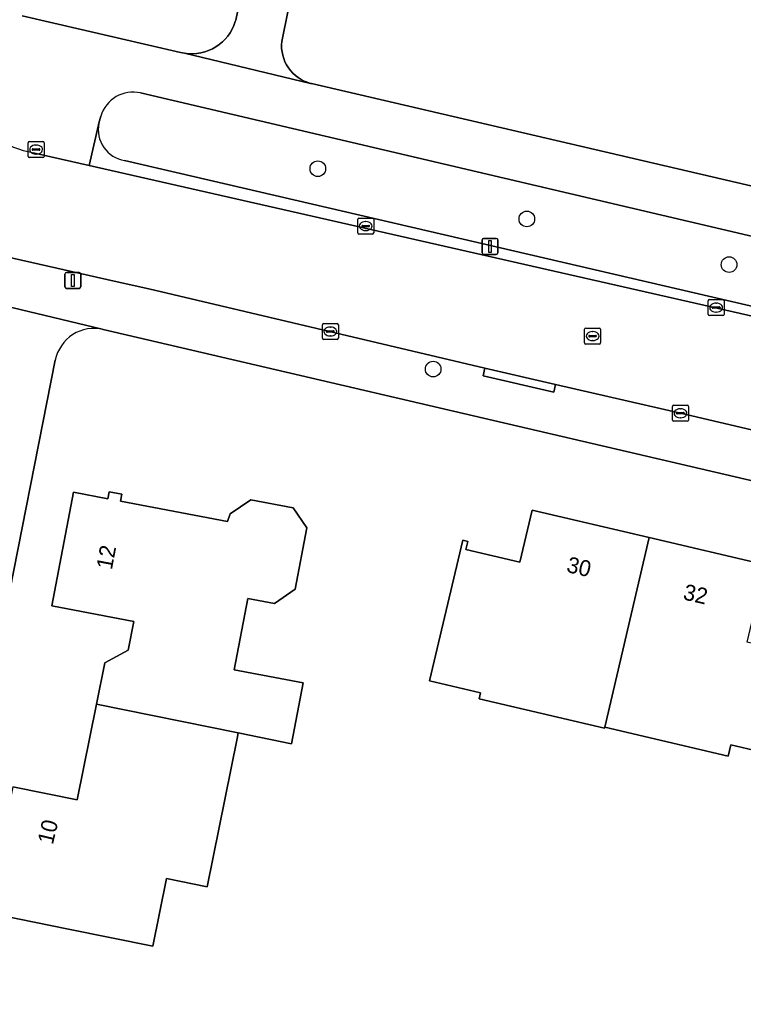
# Model space of a CAD drawing. Extents: x 162184 to 163154, y 385507 to 386516.
# Drawn here: x 162501.1 to 162546.4, y 385816.4 to 385877.3 of the extents above; entities that cross this region are included whole.
import ezdxf

# ---------------------------------------------------------------- set-up
doc = ezdxf.new("R2010")
doc.units = 0
for name, color, linetype in [('IMGEO_Boom', 7, 'Continuous'), ('IMGEO_Erf', 7, 'Continuous'), ('IMGEO_Groenvoorziening', 7, 'Continuous'), ('IMGEO_Kolk', 7, 'Continuous'), ('IMGEO_Lichtmast', 7, 'Continuous'), ('IMGEO_Pand', 7, 'Continuous'), ('IMGEO_Pand_nummerreeks', 7, 'Continuous'), ('IMGEO_Rijbaan_lokaal_open', 7, 'Continuous'), ('IMGEO_Rioolput', 7, 'Continuous'), ('IMGEO_Voetpad_open', 7, 'Continuous')]:
    doc.layers.add(name, color=color, linetype=linetype)

msp = doc.modelspace()

# ---------------------------------------------------------------- linework, layer by layer
at = {"layer": 'IMGEO_Boom'}
for centre in [(162519.792, 385867.979), (162532.864, 385864.836), (162545.515, 385861.981), (162527.005, 385855.455)]:
    msp.add_circle(centre, 0.489, dxfattribs=at)
at = {"layer": 'IMGEO_Erf'}
for points in [[(162530.251, 385938.589), (162517.573, 385876.141), (162517.539, 385875.927), (162517.525, 385875.711), (162517.53, 385875.495), (162517.554, 385875.28), (162517.597, 385875.068), (162517.659, 385874.861), (162517.739, 385874.66), (162517.837, 385874.467), (162517.952, 385874.284), (162518.083, 385874.111), (162518.228, 385873.951), (162518.388, 385873.805), (162518.559, 385873.673), (162518.742, 385873.557), (162518.935, 385873.459), (162519.135, 385873.377), (162519.342, 385873.314), (162519.391, 385873.302), (162708.853, 385829.198)], [(162699.173, 385813.033), (162656.753, 385822.985), (162635.665, 385827.646), (162589.44, 385838.573), (162506.371, 385857.936)], [(162503.373, 385856.006), (162500, 385838.961), (162491.51, 385796.057)], [(162500.718, 385829.346), (162504.748, 385828.532), (162505.954, 385834.504), (162506.479, 385837.102), (162507.941, 385837.89), (162508.283, 385839.679), (162503.148, 385840.658), (162504.503, 385847.764), (162506.65, 385847.354), (162506.732, 385847.779), (162507.526, 385847.628), (162507.444, 385847.194), (162514.139, 385845.929), (162514.311, 385846.403), (162515.601, 385847.28), (162518.253, 385846.774), (162519.102, 385845.525), (162518.372, 385841.694), (162517.075, 385840.81), (162515.417, 385841.125), (162514.567, 385836.666), (162518.88, 385835.845), (162518.156, 385832.041), (162514.819, 385832.715), (162514.746, 385832.356), (162512.872, 385823.1), (162510.331, 385823.614), (162509.477, 385819.385), (162504.208, 385820.449), (162500, 385821.299)], [(162549.176, 385831.126), (162545.626, 385831.959), (162545.464, 385831.267), (162537.747, 385833.078), (162537.73, 385833.003), (162529.874, 385834.847), (162529.961, 385835.216), (162526.786, 385835.962), (162528.853, 385844.76), (162529.164, 385844.686), (162529.045, 385844.179), (162532.432, 385843.383), (162533.198, 385846.644), (162540.507, 385844.929), (162547.788, 385843.22)]]:
    msp.add_lwpolyline(points, dxfattribs=at)
msp.add_arc((162505.806, 385855.52), 2.482, 76.84914, 168.6947, dxfattribs=at)
at = {"layer": 'IMGEO_Groenvoorziening'}
for points in [[(162501.3, 385877.523), (162511.214, 385875.241), (162511.464, 385875.19), (162511.717, 385875.162), (162511.971, 385875.156), (162512.225, 385875.174), (162512.477, 385875.214), (162512.724, 385875.276), (162512.964, 385875.36), (162513.196, 385875.465), (162513.417, 385875.59), (162513.627, 385875.735), (162513.823, 385875.898), (162514.003, 385876.077), (162514.167, 385876.272), (162514.312, 385876.481), (162514.439, 385876.702), (162514.545, 385876.934), (162514.63, 385877.174), (162514.655, 385877.262), (162515.874, 385883.146)], [(162507.704, 385868.49), (162547.735, 385859.209), (162547.854, 385859.698), (162548.778, 385863.326), (162508.707, 385872.714)], [(162506.219, 385871.261), (162506.098, 385870.815)]]:
    msp.add_lwpolyline(points, dxfattribs=at)
for centre, radius, start, end in [((162508.235, 385870.666), 2.102, 77.01532, 163.55481), ((162508.015, 385870.422), 1.957, 168.42665, 260.84312)]:
    msp.add_arc(centre, radius, start, end, dxfattribs=at)
at = {"layer": 'IMGEO_Kolk'}
for p, q in [((162501.674, 385868.751), (162501.674, 385869.603)), ((162501.749, 385869.677), (162502.601, 385869.677)), ((162502.675, 385869.603), (162502.675, 385868.751)), ((162501.933, 385869.171), (162501.933, 385869.183)), ((162502.371, 385869.134), (162501.973, 385869.134)), ((162501.976, 385869.22), (162502.374, 385869.22)), ((162502.162, 385869.457), (162502.187, 385869.457)), ((162502.417, 385869.183), (162502.417, 385869.171)), ((162502.601, 385868.677), (162501.749, 385868.677)), ((162502.185, 385868.897), (162502.16, 385868.897)), ((162522.284, 385863.965), (162522.284, 385864.817)), ((162522.359, 385864.891), (162523.211, 385864.891)), ((162523.285, 385864.817), (162523.285, 385863.965)), ((162522.543, 385864.385), (162522.543, 385864.397)), ((162522.981, 385864.348), (162522.583, 385864.348)), ((162522.586, 385864.434), (162522.984, 385864.434)), ((162522.795, 385864.111), (162522.77, 385864.111)), ((162522.772, 385864.671), (162522.797, 385864.671)), ((162523.027, 385864.397), (162523.027, 385864.385)), ((162523.211, 385863.891), (162522.359, 385863.891)), ((162544.203, 385858.869), (162544.203, 385859.721)), ((162544.278, 385859.795), (162545.13, 385859.795)), ((162544.462, 385859.289), (162544.462, 385859.301)), ((162544.9, 385859.252), (162544.502, 385859.252)), ((162544.505, 385859.338), (162544.903, 385859.338)), ((162544.691, 385859.575), (162544.716, 385859.575)), ((162544.946, 385859.301), (162544.946, 385859.289)), ((162545.204, 385859.721), (162545.204, 385858.869)), ((162545.13, 385858.795), (162544.278, 385858.795)), ((162544.714, 385859.015), (162544.689, 385859.015)), ((162520.074, 385857.377), (162520.074, 385858.229)), ((162520.149, 385858.303), (162521.001, 385858.303)), ((162520.562, 385858.083), (162520.587, 385858.083)), ((162521.075, 385858.229), (162521.075, 385857.377)), ((162520.333, 385857.797), (162520.333, 385857.809)), ((162520.771, 385857.76), (162520.373, 385857.76)), ((162520.376, 385857.846), (162520.774, 385857.846)), ((162520.585, 385857.523), (162520.56, 385857.523)), ((162520.817, 385857.809), (162520.817, 385857.797)), ((162521.001, 385857.303), (162520.149, 385857.303)), ((162542.046, 385853.194), (162542.898, 385853.194)), ((162541.971, 385852.268), (162541.971, 385853.12)), ((162542.23, 385852.688), (162542.23, 385852.7)), ((162542.668, 385852.651), (162542.27, 385852.651)), ((162542.273, 385852.737), (162542.671, 385852.737)), ((162542.459, 385852.974), (162542.484, 385852.974)), ((162542.714, 385852.7), (162542.714, 385852.688)), ((162542.972, 385853.12), (162542.972, 385852.268)), ((162542.898, 385852.194), (162542.046, 385852.194)), ((162542.482, 385852.414), (162542.457, 385852.414))]:
    msp.add_line(p, q, dxfattribs=at)
for points in [[(162501.674, 385868.751), (162501.674, 385869.603)], [(162501.749, 385869.677), (162502.601, 385869.677)], [(162502.675, 385869.603), (162502.675, 385868.751)], [(162502.601, 385868.677), (162501.749, 385868.677)], [(162522.284, 385863.965), (162522.284, 385864.817)], [(162522.359, 385864.891), (162523.211, 385864.891)], [(162523.285, 385864.817), (162523.285, 385863.965)], [(162523.211, 385863.891), (162522.359, 385863.891)], [(162544.203, 385858.869), (162544.203, 385859.721)], [(162544.278, 385859.795), (162545.13, 385859.795)], [(162545.204, 385859.721), (162545.204, 385858.869)], [(162545.13, 385858.795), (162544.278, 385858.795)], [(162520.074, 385857.377), (162520.074, 385858.229)], [(162520.149, 385858.303), (162521.001, 385858.303)], [(162521.075, 385858.229), (162521.075, 385857.377)], [(162521.001, 385857.303), (162520.149, 385857.303)], [(162542.046, 385853.194), (162542.898, 385853.194)], [(162541.971, 385852.268), (162541.971, 385853.12)], [(162542.972, 385853.12), (162542.972, 385852.268)], [(162542.898, 385852.194), (162542.046, 385852.194)]]:
    msp.add_lwpolyline(points, dxfattribs=at)
for centre, radius, start, end in [((162501.751, 385869.601), 0.0765, 91.55205, 178.44795), ((162501.751, 385869.601), 0.0765, 91.55205, 178.44795), ((162502.599, 385869.601), 0.0765, 1.55205, 88.44795), ((162502.599, 385869.601), 0.0765, 1.55205, 88.44795), ((162501.973, 385869.18), 0.0403, 85.87752, 175.75265), ((162501.97, 385869.17), 0.0366, 178.93798, 274.71019), ((162502.374, 385869.177), 0.043, 264.86636, 352.45326), ((162502.378, 385869.182), 0.0386, 1.73085, 96.63898), ((162501.751, 385868.753), 0.0765, 181.55205, 268.44795), ((162501.751, 385868.753), 0.0765, 181.55205, 268.44795), ((162502.599, 385868.753), 0.0765, 271.55205, 358.44795), ((162502.599, 385868.753), 0.0765, 271.55205, 358.44795), ((162522.361, 385864.815), 0.0765, 91.55205, 178.44795), ((162522.361, 385864.815), 0.0765, 91.55205, 178.44795), ((162523.209, 385864.815), 0.0765, 1.55205, 88.44795), ((162523.209, 385864.815), 0.0765, 1.55205, 88.44795), ((162522.583, 385864.394), 0.0403, 85.87752, 175.75265), ((162522.58, 385864.384), 0.0366, 178.93798, 274.71019), ((162522.984, 385864.391), 0.043, 264.86636, 352.45326), ((162522.988, 385864.396), 0.0386, 1.73085, 96.63898), ((162522.361, 385863.967), 0.0765, 181.55205, 268.44795), ((162522.361, 385863.967), 0.0765, 181.55205, 268.44795), ((162523.209, 385863.967), 0.0765, 271.55205, 358.44795), ((162523.209, 385863.967), 0.0765, 271.55205, 358.44795), ((162544.28, 385859.719), 0.0765, 91.55205, 178.44795), ((162544.28, 385859.719), 0.0765, 91.55205, 178.44795), ((162544.502, 385859.298), 0.0403, 85.87752, 175.75265), ((162544.499, 385859.288), 0.0366, 178.93798, 274.71019), ((162544.903, 385859.295), 0.043, 264.86636, 352.45326), ((162544.907, 385859.3), 0.0386, 1.73085, 96.63898), ((162545.128, 385859.719), 0.0765, 1.55205, 88.44795), ((162545.128, 385859.719), 0.0765, 1.55205, 88.44795), ((162544.28, 385858.871), 0.0765, 181.55205, 268.44795), ((162544.28, 385858.871), 0.0765, 181.55205, 268.44795), ((162545.128, 385858.871), 0.0765, 271.55205, 358.44795), ((162545.128, 385858.871), 0.0765, 271.55205, 358.44795), ((162520.151, 385858.227), 0.0765, 91.55205, 178.44795), ((162520.151, 385858.227), 0.0765, 91.55205, 178.44795), ((162520.999, 385858.227), 0.0765, 1.55205, 88.44795), ((162520.999, 385858.227), 0.0765, 1.55205, 88.44795), ((162520.373, 385857.806), 0.0403, 85.87752, 175.75265), ((162520.37, 385857.796), 0.0366, 178.93798, 274.71019), ((162520.774, 385857.803), 0.043, 264.86636, 352.45326), ((162520.778, 385857.808), 0.0386, 1.73085, 96.63898), ((162520.151, 385857.379), 0.0765, 181.55205, 268.44795), ((162520.151, 385857.379), 0.0765, 181.55205, 268.44795), ((162520.999, 385857.379), 0.0765, 271.55205, 358.44795), ((162520.999, 385857.379), 0.0765, 271.55205, 358.44795), ((162542.048, 385853.118), 0.0765, 91.55205, 178.44795), ((162542.048, 385853.118), 0.0765, 91.55205, 178.44795), ((162542.896, 385853.118), 0.0765, 1.55205, 88.44795), ((162542.896, 385853.118), 0.0765, 1.55205, 88.44795), ((162542.27, 385852.697), 0.0403, 85.87752, 175.75265), ((162542.267, 385852.687), 0.0366, 178.93798, 274.71019), ((162542.671, 385852.694), 0.043, 264.86636, 352.45326), ((162542.675, 385852.699), 0.0386, 1.73085, 96.63898), ((162542.048, 385852.27), 0.0765, 181.55205, 268.44795), ((162542.048, 385852.27), 0.0765, 181.55205, 268.44795), ((162542.896, 385852.27), 0.0765, 271.55205, 358.44795), ((162542.896, 385852.27), 0.0765, 271.55205, 358.44795)]:
    msp.add_arc(centre, radius, start, end, dxfattribs=at)
for centre, major_axis, ratio, start_param, end_param in [((162502.161, 385869.177), (-0.387, 0.002), 0.722429, 4.712389, 7.853982), ((162502.186, 385869.177), (-0.39, 0.002), 0.717154, 1.570796, 4.712389), ((162522.771, 385864.391), (-0.387, 0.002), 0.722429, 4.712389, 7.853982), ((162522.796, 385864.391), (-0.39, 0.002), 0.717154, 1.570796, 4.712389), ((162544.69, 385859.295), (-0.387, 0.002), 0.722429, 4.712389, 7.853982), ((162544.715, 385859.295), (-0.39, 0.002), 0.717154, 1.570796, 4.712389), ((162520.561, 385857.803), (-0.387, 0.002), 0.722429, 4.712389, 7.853982), ((162520.586, 385857.803), (-0.39, 0.002), 0.717154, 1.570796, 4.712389), ((162542.458, 385852.694), (-0.387, 0.002), 0.722429, 4.712389, 7.853982), ((162542.483, 385852.694), (-0.39, 0.002), 0.717154, 1.570796, 4.712389)]:
    msp.add_ellipse(centre, major_axis=major_axis, ratio=ratio, start_param=start_param, end_param=end_param, dxfattribs=at)
at = {"layer": 'IMGEO_Lichtmast'}
for p, q in [((162530.06, 385862.724), (162530.06, 385863.524)), ((162530.06, 385863.524), (162530.06, 385862.724)), ((162530.16, 385863.624), (162530.95, 385863.624)), ((162530.95, 385863.624), (162530.16, 385863.624)), ((162531.05, 385863.524), (162531.05, 385862.724)), ((162531.05, 385862.724), (162531.05, 385863.524)), ((162530.95, 385862.624), (162530.16, 385862.624)), ((162530.16, 385862.624), (162530.95, 385862.624)), ((162503.974, 385860.597), (162503.974, 385861.397)), ((162503.974, 385861.397), (162503.974, 385860.597)), ((162504.074, 385861.497), (162504.864, 385861.497)), ((162504.864, 385861.497), (162504.074, 385861.497)), ((162504.964, 385861.397), (162504.964, 385860.597)), ((162504.964, 385860.597), (162504.964, 385861.397)), ((162504.864, 385860.497), (162504.074, 385860.497)), ((162504.074, 385860.497), (162504.864, 385860.497))]:
    msp.add_line(p, q, dxfattribs=at)
for points in [[(162530.48, 385863.499), (162530.63, 385863.499), (162530.63, 385862.749), (162530.48, 385862.749), (162530.48, 385863.499)], [(162504.394, 385861.372), (162504.544, 385861.372), (162504.544, 385860.622), (162504.394, 385860.622), (162504.394, 385861.372)]]:
    msp.add_lwpolyline(points, dxfattribs=at)
for centre, start, end in [((162530.16, 385863.524), 90, 180), ((162530.16, 385863.524), 90, 180), ((162530.95, 385863.524), 0, 90), ((162530.95, 385863.524), 360, 90), ((162530.16, 385862.724), 180, 270), ((162530.16, 385862.724), 180, 270), ((162530.95, 385862.724), 270, 0), ((162530.95, 385862.724), 270, 0), ((162504.074, 385861.397), 90, 180), ((162504.074, 385861.397), 90, 180), ((162504.864, 385861.397), 0, 90), ((162504.864, 385861.397), 360, 90), ((162504.074, 385860.597), 180, 270), ((162504.074, 385860.597), 180, 270), ((162504.864, 385860.597), 270, 0), ((162504.864, 385860.597), 270, 0)]:
    msp.add_arc(centre, 0.1, start, end, dxfattribs=at)
at = {"layer": 'IMGEO_Pand'}
for points in [[(162518.372, 385841.694), (162519.102, 385845.525), (162518.253, 385846.774), (162515.601, 385847.28), (162514.311, 385846.403), (162514.139, 385845.929), (162507.444, 385847.194), (162507.526, 385847.628), (162506.732, 385847.779), (162506.65, 385847.354), (162504.503, 385847.764), (162503.148, 385840.658), (162508.283, 385839.679), (162507.941, 385837.89), (162506.479, 385837.102), (162505.954, 385834.504), (162514.819, 385832.715), (162518.156, 385832.041), (162518.88, 385835.845), (162514.567, 385836.666), (162515.417, 385841.125), (162517.075, 385840.81)], [(162540.507, 385844.929), (162533.198, 385846.644), (162532.432, 385843.383), (162529.045, 385844.179), (162529.164, 385844.686), (162528.853, 385844.76), (162526.786, 385835.962), (162529.961, 385835.216), (162529.874, 385834.847), (162537.73, 385833.003), (162537.747, 385833.078)], [(162550.626, 385837.445), (162546.651, 385838.378), (162547.788, 385843.22), (162540.507, 385844.929), (162537.747, 385833.078), (162545.464, 385831.267), (162545.626, 385831.959), (162549.176, 385831.126)], [(162514.746, 385832.356), (162514.819, 385832.715), (162505.954, 385834.504), (162504.748, 385828.532), (162500.718, 385829.346), (162500, 385825.788), (162499.835, 385824.97), (162499.677, 385825.002), (162499.318, 385823.224), (162499.653, 385823.156), (162499.306, 385821.439), (162500, 385821.299), (162504.208, 385820.449), (162509.477, 385819.385), (162510.331, 385823.614), (162512.872, 385823.1)]]:
    msp.add_lwpolyline(points, close=True, dxfattribs=at)
at = {"layer": 'IMGEO_Rijbaan_lokaal_open'}
for points in [[(162610.474, 385844.009), (162603.528, 385845.611), (162603.422, 385845.63), (162587.987, 385849.233), (162580.509, 385850.96), (162566.089, 385854.314), (162562.139, 385855.233), (162554.096, 385857.098), (162547.598, 385858.61), (162505.494, 385868.182), (162501.99, 385868.979)], [(162499.218, 385862.73), (162507.056, 385860.958), (162509.218, 385860.468), (162530.239, 385855.522), (162534.656, 385854.499), (162542.472, 385852.695), (162549.662, 385851.015), (162557.296, 385849.219), (162561.487, 385848.231), (162572.263, 385845.731), (162579.333, 385844.08), (162579.558, 385844.019), (162594.175, 385840.627), (162598.333, 385839.654), (162598.843, 385839.529), (162602.566, 385838.654), (162616.709, 385835.361), (162617.593, 385835.175), (162624.031, 385833.683), (162636.751, 385830.699)]]:
    msp.add_lwpolyline(points, dxfattribs=at)
msp.add_arc((162503.102, 385875.08), 6.201, 165.95967, 259.67133, dxfattribs=at)
at = {"layer": 'IMGEO_Rioolput'}
for p, q in [((162536.553, 385858.016), (162537.405, 385858.016)), ((162536.478, 385857.09), (162536.478, 385857.942)), ((162536.737, 385857.51), (162536.737, 385857.522)), ((162537.175, 385857.473), (162536.777, 385857.473)), ((162536.78, 385857.559), (162537.178, 385857.559)), ((162536.966, 385857.796), (162536.991, 385857.796)), ((162537.221, 385857.522), (162537.221, 385857.51)), ((162537.479, 385857.942), (162537.479, 385857.09)), ((162537.405, 385857.016), (162536.553, 385857.016)), ((162536.989, 385857.236), (162536.964, 385857.236))]:
    msp.add_line(p, q, dxfattribs=at)
for points in [[(162536.553, 385858.016), (162537.405, 385858.016)], [(162536.478, 385857.09), (162536.478, 385857.942)], [(162537.479, 385857.942), (162537.479, 385857.09)], [(162537.405, 385857.016), (162536.553, 385857.016)]]:
    msp.add_lwpolyline(points, dxfattribs=at)
for centre, radius, start, end in [((162536.555, 385857.94), 0.0765, 91.55205, 178.44795), ((162536.555, 385857.94), 0.0765, 91.55205, 178.44795), ((162537.403, 385857.94), 0.0765, 1.55205, 88.44795), ((162537.403, 385857.94), 0.0765, 1.55205, 88.44795), ((162536.777, 385857.519), 0.0403, 85.87752, 175.75265), ((162536.774, 385857.509), 0.0366, 178.93798, 274.71019), ((162537.178, 385857.516), 0.043, 264.86636, 352.45326), ((162537.182, 385857.521), 0.0386, 1.73085, 96.63898), ((162536.555, 385857.092), 0.0765, 181.55205, 268.44795), ((162536.555, 385857.092), 0.0765, 181.55205, 268.44795), ((162537.403, 385857.092), 0.0765, 271.55205, 358.44795), ((162537.403, 385857.092), 0.0765, 271.55205, 358.44795)]:
    msp.add_arc(centre, radius, start, end, dxfattribs=at)
for centre, major_axis, ratio, start_param, end_param in [((162536.965, 385857.516), (-0.387, 0.002), 0.722429, 4.712389, 7.853982), ((162536.99, 385857.516), (-0.39, 0.002), 0.717154, 1.570796, 4.712389)]:
    msp.add_ellipse(centre, major_axis=major_axis, ratio=ratio, start_param=start_param, end_param=end_param, dxfattribs=at)
at = {"layer": 'IMGEO_Voetpad_open'}
for points in [[(162515.874, 385883.146), (162514.655, 385877.262), (162514.63, 385877.174), (162514.545, 385876.934), (162514.439, 385876.702), (162514.312, 385876.481), (162514.167, 385876.272), (162514.003, 385876.077), (162513.823, 385875.898), (162513.627, 385875.735), (162513.417, 385875.59), (162513.196, 385875.465), (162512.964, 385875.36), (162512.724, 385875.276), (162512.477, 385875.214), (162512.225, 385875.174), (162511.971, 385875.156), (162511.717, 385875.162), (162511.464, 385875.19), (162519.342, 385873.314), (162519.135, 385873.377), (162518.935, 385873.459), (162518.742, 385873.557), (162518.559, 385873.673), (162518.388, 385873.805), (162518.228, 385873.951), (162518.083, 385874.111), (162517.952, 385874.284), (162517.837, 385874.467), (162517.739, 385874.66), (162517.659, 385874.861), (162517.597, 385875.068), (162517.554, 385875.28), (162517.53, 385875.495), (162517.525, 385875.711), (162517.539, 385875.927), (162517.573, 385876.141), (162530.251, 385938.589)], [(162519.391, 385873.302), (162519.342, 385873.314), (162511.464, 385875.19), (162511.214, 385875.241), (162501.3, 385877.523)], [(162708.853, 385829.198), (162519.391, 385873.302)], [(162508.707, 385872.714), (162548.778, 385863.326), (162547.854, 385859.698), (162554.349, 385858.155), (162555.24, 385861.819), (162563.244, 385859.94), (162562.391, 385856.309), (162566.335, 385855.374), (162567.186, 385859.042), (162581.626, 385855.694), (162580.763, 385852.023), (162588.234, 385850.294), (162589.092, 385853.966), (162604.684, 385850.342), (162603.81, 385846.69), (162610.724, 385845.075), (162611.587, 385848.755), (162626.899, 385845.211), (162626.065, 385841.525), (162632.616, 385839.977)], [(162501.99, 385868.979), (162505.494, 385868.182), (162506.071, 385870.723), (162506.098, 385870.815), (162506.219, 385871.261)], [(162506.098, 385870.815), (162506.071, 385870.723), (162505.494, 385868.182), (162547.598, 385858.61), (162547.735, 385859.209), (162507.704, 385868.49)], [(162549.662, 385851.015), (162542.472, 385852.695), (162534.656, 385854.499), (162534.544, 385854.012), (162530.127, 385855.035), (162530.239, 385855.522), (162509.218, 385860.468), (162507.056, 385860.958), (162499.218, 385862.73)], [(162496.672, 385860.214), (162498.12, 385859.904), (162506.313, 385857.957), (162506.371, 385857.936), (162589.44, 385838.573), (162635.665, 385827.646), (162656.753, 385822.985), (162699.173, 385813.033)], [(162506.371, 385857.936), (162506.313, 385857.957), (162498.12, 385859.904)], [(162500, 385838.961), (162503.373, 385856.006)]]:
    msp.add_lwpolyline(points, dxfattribs=at)
msp.add_lwpolyline([(162530.239, 385855.522), (162530.127, 385855.035), (162534.544, 385854.012), (162534.656, 385854.499)], close=True, dxfattribs=at)
for centre, radius, start, end in [((162503.102, 385875.08), 6.201, 165.95967, 259.67133), ((162508.235, 385870.666), 2.102, 77.01532, 163.55481), ((162508.015, 385870.422), 1.957, 168.42665, 260.84312), ((162505.806, 385855.52), 2.482, 76.84914, 168.6947)]:
    msp.add_arc(centre, radius, start, end, dxfattribs=at)

# ---------------------------------------------------------------- texts
at = {"layer": 'IMGEO_Pand_nummerreeks'}
for s, rotation, p in [('12', 79.20569, (162506.909, 385842.872)), ('30', 346.79332, (162535.294, 385842.783)), ('32', 346.79276, (162542.584, 385841.072)), ('10', 76.52424, (162503.217, 385825.697))]:
    msp.add_text(s, height=1, rotation=rotation, dxfattribs=at).set_placement(p)

doc.saveas('drawing.dxf')
